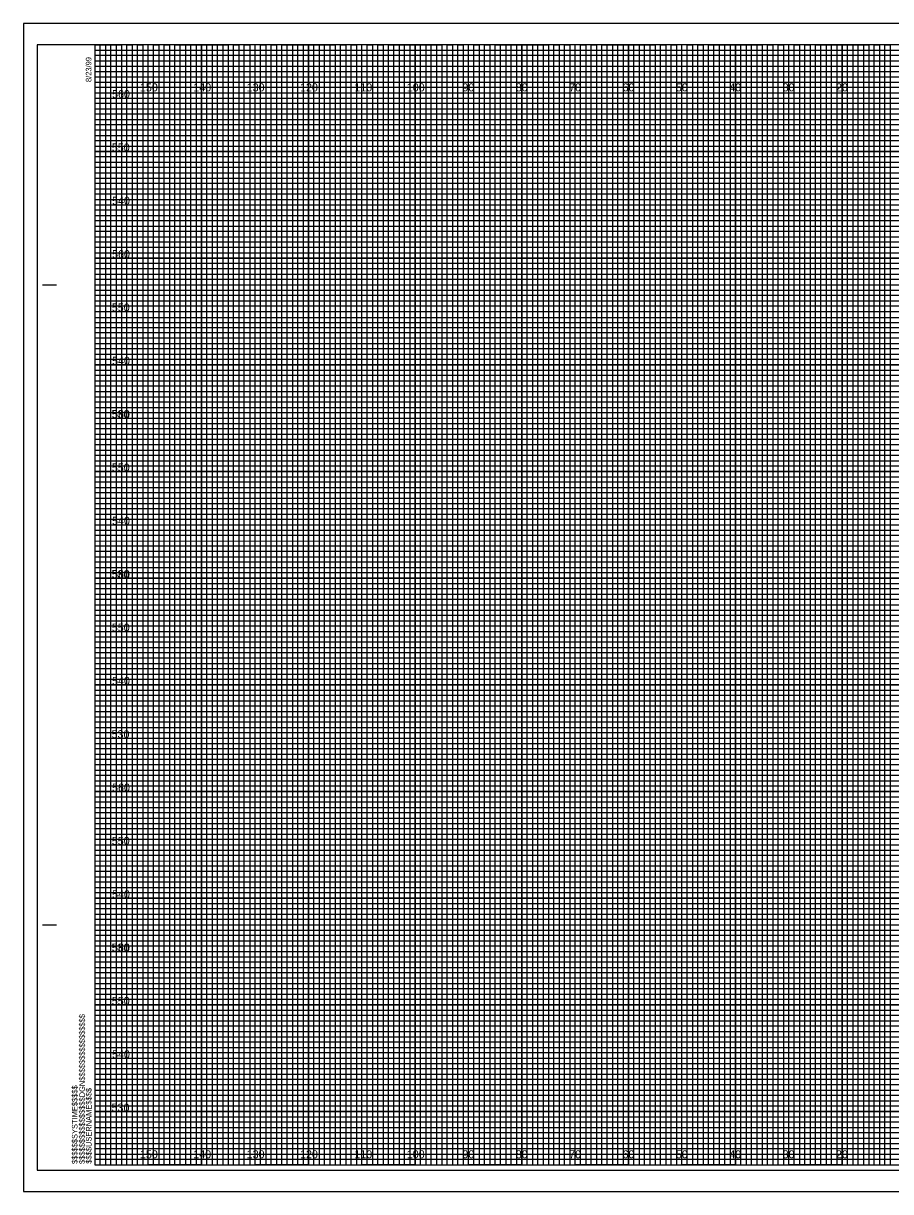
# Model space of a CAD drawing. Extents: x -13 to 323, y 435 to 654.
# Drawn here: x -13.4 to 149.1, y 435 to 654 of the extents above; entities that cross this region are included whole.
import ezdxf

# ---------------------------------------------------------------- set-up
doc = ezdxf.new("R2010")
doc.units = 0
for name, color, linetype in [('Exist Cross Section Cell', 7, 'Continuous'), ('Exist XS Ground Line', 7, 'Continuous'), ('Prop CMT Pvmt Course 2', 7, 'Continuous'), ('Prop CMT Pvmt Course 3', 7, 'Continuous'), ('Prop CMT Pvmt Surface', 7, 'Continuous'), ('Prop CMT Pvmt Wedge Surface 1', 7, 'Continuous'), ('Prop CMT Pvmt Wedge Surface 2', 7, 'Continuous'), ('Prop CMT Shld Paved Course 1', 7, 'Continuous'), ('Prop CMT Shld Paved Course 2', 7, 'Continuous'), ('Prop CMT Slope Grass', 7, 'Continuous'), ('Prop CMT Subgrade Earthwork', 7, 'Continuous')]:
    doc.layers.add(name, color=color, linetype=linetype)

msp = doc.modelspace()

# ---------------------------------------------------------------- linework, layer by layer
at = {"layer": 'Exist XS Ground Line'}
for p, q in [((10, 650), (0, 650)), ((10, 440), (10, 650)), ((30, 650), (20, 650)), ((20, 650), (20, 440)), ((30, 440), (30, 650)), ((50, 650), (40, 650)), ((40, 650), (40, 440)), ((50, 440), (50, 650)), ((70, 650), (60, 650)), ((60, 650), (60, 440)), ((70, 440), (70, 650)), ((90, 650), (80, 650)), ((80, 650), (80, 440)), ((90, 440), (90, 650)), ((110, 650), (100, 650)), ((100, 650), (100, 440)), ((110, 440), (110, 650)), ((130, 650), (120, 650)), ((120, 650), (120, 440)), ((130, 440), (130, 650)), ((150, 650), (140, 650)), ((140, 650), (140, 440)), ((20, 440), (10, 440)), ((40, 440), (30, 440)), ((60, 440), (50, 440)), ((80, 440), (70, 440)), ((100, 440), (90, 440)), ((120, 440), (110, 440)), ((140, 440), (130, 440))]:
    msp.add_line(p, q, dxfattribs=at)
for points in [[(0, 640), (320, 640), (320, 630), (0, 630)], [(0, 620), (320, 620), (320, 610), (0, 610)], [(0, 600), (320, 600), (320, 590), (0, 590)], [(0, 580), (320, 580), (320, 570), (0, 570)], [(0, 560), (320, 560), (320, 550), (0, 550)], [(0, 540), (320, 540), (320, 530), (0, 530)], [(0, 520), (320, 520), (320, 510), (0, 510)], [(0, 500), (320, 500), (320, 490), (0, 490)], [(0, 480), (320, 480), (320, 470), (0, 470)], [(0, 460), (320, 460), (320, 450), (0, 450)]]:
    msp.add_lwpolyline(points, dxfattribs=at)
at = {"layer": 'Prop CMT Pvmt Course 2'}
msp.add_lwpolyline([(-13.4, 435), (323.3, 435), (323.3, 654), (-13.4, 654)], close=True, dxfattribs=at)
at = {"layer": 'Prop CMT Pvmt Course 3'}
msp.add_lwpolyline([(-10.8, 439), (322.4, 439), (322.4, 650), (-10.8, 650)], close=True, dxfattribs=at)
at = {"layer": 'Prop CMT Pvmt Surface'}
for p, q in [((10, 440), (10, 650)), ((20, 440), (20, 650)), ((30, 440), (30, 650)), ((40, 440), (40, 650)), ((50, 440), (50, 650)), ((60, 440), (60, 650)), ((70, 440), (70, 650)), ((80, 440), (80, 650)), ((90, 440), (90, 650)), ((100, 440), (100, 650)), ((110, 440), (110, 650)), ((120, 440), (120, 650)), ((130, 440), (130, 650)), ((140, 440), (140, 650)), ((0, 640), (320, 640)), ((0, 630), (320, 630)), ((0, 620), (320, 620)), ((0, 610), (320, 610)), ((0, 600), (320, 600)), ((0, 590), (320, 590)), ((0, 580), (320, 580)), ((0, 570), (320, 570)), ((0, 560), (320, 560)), ((0, 550), (320, 550)), ((0, 540), (320, 540)), ((0, 530), (320, 530)), ((0, 520), (320, 520)), ((0, 510), (320, 510)), ((0, 500), (320, 500)), ((0, 490), (320, 490)), ((0, 480), (320, 480)), ((0, 470), (320, 470)), ((0, 460), (320, 460)), ((0, 450), (320, 450))]:
    msp.add_line(p, q, dxfattribs=at)
at = {"layer": 'Prop CMT Pvmt Wedge Surface 1'}
for p, q in [((323.3, 654), (-13.4, 654)), ((-13.4, 654), (-13.4, 435)), ((-13.4, 435), (323.3, 435))]:
    msp.add_line(p, q, dxfattribs=at)
at = {"layer": 'Prop CMT Shld Paved Course 1'}
for p, q in [((-9.8, 605), (-7.3, 605)), ((-9.7, 605), (-7.2, 605)), ((-9.8, 485), (-7.3, 485)), ((-9.7, 485), (-7.2, 485)), ((0, 440), (0, 440)), ((0, 440), (0, 440)), ((0, 440), (0, 440)), ((0, 440), (0, 440)), ((0, 440), (0, 440)), ((0, 440), (0, 440)), ((0, 440), (0, 440))]:
    msp.add_line(p, q, dxfattribs=at)
msp.add_lwpolyline([(320, 650), (0, 650), (0, 440), (320, 440)], close=True, dxfattribs=at)
at = {"layer": 'Prop CMT Shld Paved Course 2'}
for points in [[(0, 440), (1, 440), (1, 650), (2, 650), (2, 440)], [(2, 440), (3, 440), (3, 650), (4, 650), (4, 440)], [(5, 440), (6, 440), (6, 650), (7, 650), (7, 440)], [(7, 440), (8, 440), (8, 650), (9, 650), (9, 440)], [(10, 440), (11, 440), (11, 650), (12, 650), (12, 440)], [(12, 440), (13, 440), (13, 650), (14, 650), (14, 440)], [(15, 440), (16, 440), (16, 650), (17, 650), (17, 440)], [(17, 440), (18, 440), (18, 650), (19, 650), (19, 440)], [(20, 440), (21, 440), (21, 650), (22, 650), (22, 440)], [(22, 440), (23, 440), (23, 650), (24, 650), (24, 440)], [(25, 440), (26, 440), (26, 650), (27, 650), (27, 440)], [(27, 440), (28, 440), (28, 650), (29, 650), (29, 440)], [(30, 440), (31, 440), (31, 650), (32, 650), (32, 440)], [(32, 440), (33, 440), (33, 650), (34, 650), (34, 440)], [(35, 440), (36, 440), (36, 650), (37, 650), (37, 440)], [(37, 440), (38, 440), (38, 650), (39, 650), (39, 440)], [(40, 440), (41, 440), (41, 650), (42, 650), (42, 440)], [(42, 440), (43, 440), (43, 650), (44, 650), (44, 440)], [(45, 440), (46, 440), (46, 650), (47, 650), (47, 440)], [(47, 440), (48, 440), (48, 650), (49, 650), (49, 440)], [(50, 440), (51, 440), (51, 650), (52, 650), (52, 440)], [(52, 440), (53, 440), (53, 650), (54, 650), (54, 440)], [(55, 440), (56, 440), (56, 650), (57, 650), (57, 440)], [(57, 440), (58, 440), (58, 650), (59, 650), (59, 440)], [(60, 440), (61, 440), (61, 650), (62, 650), (62, 440)], [(62, 440), (63, 440), (63, 650), (64, 650), (64, 440)], [(65, 440), (66, 440), (66, 650), (67, 650), (67, 440)], [(67, 440), (68, 440), (68, 650), (69, 650), (69, 440)], [(70, 440), (71, 440), (71, 650), (72, 650), (72, 440)], [(72, 440), (73, 440), (73, 650), (74, 650), (74, 440)], [(75, 440), (76, 440), (76, 650), (77, 650), (77, 440)], [(77, 440), (78, 440), (78, 650), (79, 650), (79, 440)], [(80, 440), (81, 440), (81, 650), (82, 650), (82, 440)], [(82, 440), (83, 440), (83, 650), (84, 650), (84, 440)], [(85, 440), (86, 440), (86, 650), (87, 650), (87, 440)], [(87, 440), (88, 440), (88, 650), (89, 650), (89, 440)], [(90, 440), (91, 440), (91, 650), (92, 650), (92, 440)], [(92, 440), (93, 440), (93, 650), (94, 650), (94, 440)], [(95, 440), (96, 440), (96, 650), (97, 650), (97, 440)], [(97, 440), (98, 440), (98, 650), (99, 650), (99, 440)], [(100, 440), (101, 440), (101, 650), (102, 650), (102, 440)], [(102, 440), (103, 440), (103, 650), (104, 650), (104, 440)], [(105, 440), (106, 440), (106, 650), (107, 650), (107, 440)], [(107, 440), (108, 440), (108, 650), (109, 650), (109, 440)], [(110, 440), (111, 440), (111, 650), (112, 650), (112, 440)], [(112, 440), (113, 440), (113, 650), (114, 650), (114, 440)], [(115, 440), (116, 440), (116, 650), (117, 650), (117, 440)], [(117, 440), (118, 440), (118, 650), (119, 650), (119, 440)], [(120, 440), (121, 440), (121, 650), (122, 650), (122, 440)], [(122, 440), (123, 440), (123, 650), (124, 650), (124, 440)], [(125, 440), (126, 440), (126, 650), (127, 650), (127, 440)], [(127, 440), (128, 440), (128, 650), (129, 650), (129, 440)], [(130, 440), (131, 440), (131, 650), (132, 650), (132, 440)], [(132, 440), (133, 440), (133, 650), (134, 650), (134, 440)], [(135, 440), (136, 440), (136, 650), (137, 650), (137, 440)], [(137, 440), (138, 440), (138, 650), (139, 650), (139, 440)], [(140, 440), (141, 440), (141, 650), (142, 650), (142, 440)], [(142, 440), (143, 440), (143, 650), (144, 650), (144, 440)], [(145, 440), (146, 440), (146, 650), (147, 650), (147, 440)], [(147, 440), (148, 440), (148, 650), (149, 650), (149, 440)]]:
    msp.add_lwpolyline(points, dxfattribs=at)
at = {"layer": 'Prop CMT Slope Grass'}
for p, q in [((0, 649), (260, 649)), ((260, 647.98), (0, 647.98)), ((0, 647.98), (0, 647)), ((0, 647), (260, 647)), ((260, 645.89), (0, 645.89)), ((0, 645.89), (0, 644)), ((0, 644), (320, 644))]:
    msp.add_line(p, q, dxfattribs=at)
for points in [[(0, 643), (270, 643), (320, 643), (320, 642), (0, 642)], [(0, 641), (320, 641), (320, 639), (0, 639)], [(0, 638), (320, 638), (320, 637), (0, 636.98)], [(0, 636), (320, 636), (320, 634), (0, 634)], [(0, 633), (320, 633), (320, 632), (0, 632)], [(0, 631), (320, 631), (320, 629), (0, 629)], [(0, 628), (320, 628), (320, 627), (0, 627)], [(0, 626), (320, 626), (320, 624), (0, 624)], [(0, 623), (320, 623), (320, 622), (0, 622)], [(0, 621), (320, 621), (320, 619), (0, 619)], [(0, 618), (320, 618), (320, 617), (0, 617)], [(0, 616), (320, 616), (320, 613.95), (320, 613), (320, 612), (0, 612)], [(0, 614), (320, 614), (320, 613), (0, 613)], [(0, 611), (320, 611), (320, 609), (0, 609.03)], [(0, 609.03), (320, 609), (320, 608), (0, 608)], [(0, 607), (320, 607), (320, 606), (0, 606)], [(0, 604), (320, 604), (320, 603), (0, 603)], [(0, 602), (320, 602), (320, 601), (0, 601)], [(-0.07, 598.89), (320, 598.89), (320, 597.88), (-0.07, 597.88)], [(0, 597), (320, 597), (320, 596), (0, 596)], [(0, 594), (320, 594), (320, 593), (0, 593)], [(0, 592), (320, 592), (320, 591), (0, 591)], [(0, 589), (320, 589), (320, 588), (0, 588)], [(0, 587), (320, 587), (320, 586), (0, 586)], [(0, 584), (320, 584), (320, 583), (0, 583)], [(0, 582), (320, 582), (320, 581), (0, 581)], [(0, 579), (320, 579), (319.99, 577.98), (0, 578)], [(0, 577), (320, 577), (320, 576), (0, 576)], [(0, 574), (320, 574), (320, 573), (0, 573)], [(0, 572), (320, 572), (320, 571), (0, 571)], [(0, 569), (320, 569), (320, 568), (0, 568)], [(0, 567), (320, 567), (320, 566), (0, 566)], [(0, 564), (320, 564), (320, 563), (0, 563)], [(0, 562), (320, 562), (320, 561), (0, 561)], [(0, 559), (320, 559), (320, 558), (0, 558)], [(0, 556.99), (320.07, 556.91), (320, 556), (0, 556)], [(0, 554), (320, 554), (320, 553), (0, 553)], [(0, 552), (320, 552), (320, 551), (0, 551)], [(0, 549), (320, 549), (320, 548), (0, 548)], [(0, 547), (320, 547), (320, 546), (0, 546)], [(0, 544), (320, 544), (320, 543), (0, 543)], [(0, 542), (320, 542), (320, 541), (0, 541)], [(0, 539), (320, 539), (320, 538), (0, 538)], [(0, 537), (320, 537), (320, 536), (0, 536)], [(0, 534), (320, 534), (320, 533), (0, 533)], [(0, 532), (320, 532), (320, 531), (0, 531)], [(0, 529), (320, 529), (320, 528), (0, 528)], [(0, 527), (320, 527), (320, 526), (0, 526)], [(0, 524), (320, 524), (320, 523), (0, 523)], [(0, 522), (320, 522), (320, 521), (0, 521)], [(0, 519), (320, 519), (319.99, 517.98), (0, 518)], [(0, 517), (320, 517), (320, 516), (0, 516)], [(0, 514), (320, 514), (320, 513), (0, 513)], [(0, 512), (320, 512), (320, 511), (0, 511)], [(0, 509), (320, 509), (320, 508), (0, 508)], [(0, 507), (320, 507), (320, 506), (0, 506)], [(0, 504), (320, 504), (320, 503), (0, 503)], [(0, 502), (320, 502), (320, 501), (0, 501)], [(0, 499), (320, 499), (320, 498), (0, 498)], [(0, 496.99), (320.07, 496.91), (320, 496), (0, 496)], [(0, 494), (320, 494), (320, 493), (0, 493)], [(0, 492), (320, 492), (320, 491), (0, 491)], [(0, 489), (320, 489), (320, 488), (0, 488)], [(0, 487), (320, 487), (320, 486), (0, 486)], [(0, 484), (320, 484), (320, 483), (0, 483)], [(0, 482), (320, 482), (320, 481), (0, 481)], [(0, 479), (320, 479), (320, 478), (0, 478)], [(0, 477), (320, 477), (320, 476), (0, 476)], [(0, 474), (320, 474), (320, 473), (0, 473)], [(0, 472), (320, 472), (320, 471), (0, 471)], [(0, 469), (320, 469), (320, 468), (0, 468)], [(0, 467), (320, 467), (320, 466), (0, 466)], [(0, 464), (320, 464), (320, 463), (0, 463)], [(0, 462), (320, 462), (320, 461), (0, 461)], [(0, 459), (320, 459), (320, 458), (0, 458)], [(0, 457), (320, 457), (320, 456), (0, 456)], [(0, 454), (320, 454), (320, 453), (0, 453)], [(0, 452), (320, 452), (320, 451), (0, 451)], [(0, 449), (320, 449), (320, 448), (0, 448)], [(0, 447), (320, 447), (320, 446), (0, 446)], [(0, 444), (320, 444), (320, 443), (0, 443)], [(0, 442), (320, 442), (320, 441), (0, 441)]]:
    msp.add_lwpolyline(points, dxfattribs=at)
at = {"layer": 'Prop CMT Subgrade Earthwork'}
for points in [[(0, 650), (5, 650), (5, 440), (15, 440), (15, 650), (25, 650), (25, 440), (35, 440), (35, 650), (45, 650), (45, 440), (55, 440), (55, 650), (65, 650), (65, 440), (75, 440), (75, 650), (85, 650), (85, 440), (95, 440), (95, 650), (105, 650), (105, 440), (115, 440), (115, 650), (125, 650), (125, 440), (135, 440), (135, 650), (145, 650), (145, 440), (155, 440)], [(0, 645), (275, 645)], [(0, 625), (320, 625), (320, 635), (0, 635)], [(0, 605), (320, 605), (320, 615), (0, 615)], [(0, 585), (320, 585), (320, 595), (0, 595)], [(0, 565), (320, 565), (320, 575), (0, 575)], [(0, 545), (320, 545), (320, 555), (0, 555)], [(0, 525), (320, 525), (320, 535), (0, 535)], [(0, 505), (320, 505), (320, 515), (0, 515)], [(0, 485), (320, 485), (320, 495), (0, 495)], [(0, 465), (320, 465), (320, 475), (0, 475)], [(0, 445), (320, 445), (320, 455), (0, 455)]]:
    msp.add_lwpolyline(points, dxfattribs=at)

# ---------------------------------------------------------------- texts
at = {"layer": 'Exist Cross Section Cell'}
for s, p in [('150', (8.44, 641.25)), ('140', (18.44, 641.25)), ('130', (28.44, 641.25)), ('120', (38.44, 641.25)), ('110', (48.62, 641.25)), ('100', (58.44, 641.25)), ('90', (68.86, 641.25)), ('80', (78.86, 641.25)), ('70', (88.86, 641.25)), ('60', (98.86, 641.25)), ('50', (108.86, 641.25)), ('40', (118.86, 641.25)), ('30', (128.86, 641.25)), ('20', (138.86, 641.25)), ('150', (8.44, 441.25)), ('140', (18.44, 441.25)), ('130', (28.44, 441.25)), ('120', (38.44, 441.25)), ('110', (48.62, 441.25)), ('100', (58.44, 441.25)), ('90', (68.86, 441.25)), ('80', (78.86, 441.25)), ('70', (88.86, 441.25)), ('60', (98.86, 441.25)), ('50', (108.86, 441.25)), ('40', (118.86, 441.25)), ('30', (128.86, 441.25)), ('20', (138.86, 441.25))]:
    msp.add_text(s, height=1.5, dxfattribs=at).set_placement(p)
at = {"layer": 'Prop CMT Pvmt Wedge Surface 2'}
for s, p in [('560', (3.22, 640)), ('550', (3.17, 630)), ('540', (3.22, 620)), ('560', (3.22, 610)), ('550', (3.17, 600)), ('540', (3.22, 590)), ('530', (3.13, 580)), ('560', (3.22, 580)), ('550', (3.17, 570)), ('540', (3.22, 560)), ('530', (3.13, 550)), ('560', (3.22, 550)), ('550', (3.17, 540)), ('540', (3.22, 530)), ('530', (3.13, 520)), ('560', (3.22, 510)), ('550', (3.17, 500)), ('540', (3.22, 490)), ('530', (3.13, 480)), ('560', (3.22, 480)), ('550', (3.17, 470)), ('540', (3.22, 460)), ('530', (3.13, 450))]:
    msp.add_text(s, height=1.5, dxfattribs=at).set_placement(p)
at = {"layer": 'Prop CMT Shld Paved Course 1'}
for s, p in [('8/23/99', (-0.65, 643)), ('$$$$$$$$$$$$$$$$DGN$$$$$$$$$$$$$$$$', (-1.88, 440.18)), ('$$$$$$SYSTIME$$$$$', (-3.26, 440.18)), ('$$$$USERNAME$$$$', (-0.62, 440.23))]:
    msp.add_text(s, height=1.05, rotation=90, dxfattribs=at).set_placement(p)

doc.saveas('drawing.dxf')
